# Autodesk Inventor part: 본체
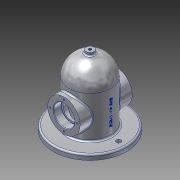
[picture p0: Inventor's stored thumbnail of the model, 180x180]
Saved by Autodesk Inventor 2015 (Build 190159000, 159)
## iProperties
Created: 2019-11
Part Number: 본체
Material: 알루미늄 6061
Document SubType Name: Modeling
Designer: LINEART-SSD.D4.16.05
Density: 2.7 g/cm^3
Appearance: 알루미늄 - 평지
Mass: 1106.12 g
Surface Area: 883.263 cm^2
Volume: 409.676 cm^3
Author: LINEART-SSD.D4.16.05
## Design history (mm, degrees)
sketch "스케치1"
  geometry: C1 r 70 at (0, 0); 1 further point
  constraints: 1 centre point, 1 coincident
  dimensions: "d0" = 140 diameter of C1
extrude "돌출1" new body sketch "스케치1" distance "d1" = 10; taper "d2" = 0 deg
sketch "스케치2"
  geometry: C1 r 40 at (0, 0); 1 further point
  constraints: 1 centre point, 1 coincident
  dimensions: "d3" = 80 diameter of C1
extrude "돌출2" join sketch "스케치2" distance "d4" = 80; taper "d5" = 0 deg
sketch "스케치6"
  geometry: L1 (90, -40)-(90, 40) reference; L2 (90, 0)-(90, -40); L3 (130, 0)-(90, 0); A1 r 40 centre (90, 0) between (90, -40) and (130, 0); 1 further point
  constraints: 4 end point, 2 point on circle, 1 centre point, 1 collinear, 1 horizontal, 1 midpoint
  dimensions: "d14" = 40 radius of A1 (derived)
revolve "회전2" sketch "스케치6" stored, may be unused: angle "d15" = 90 deg
node "작업 평면2"
sketch "스케치7"
  geometry: C1 r 7.5 at (0, 0); 1 further point
  constraints: 1 centre point, 1 coincident
  dimensions: "d16" = 15 diameter of C1
extrude "돌출4" join sketch "스케치7" distance "d17" = 5; taper "d18" = 0 deg; dims "d38" = 3, "d39" = 0
node "작업 평면3"
sketch "스케치9"
  geometry: L1 (10, -40)-(90, -40) reference; L2 (135, -7.5)-(135, 7.5) reference; C1 r 31 at (50, 0); 3 further points
  constraints: 2 midpoint, 1 centre point, 1 horizontal alignment, 1 vertical alignment
  dimensions: "d21" = 62 diameter of C1
extrude "돌출5" join sketch "스케치9" distance "d22" = 10; taper "d24" = 0 deg; dims "d23" = 30, "d25" = 0
sketch "스케치10"
  geometry: C1 r 31 at (0, 0) reference; C2 r 20 at (0, 0); 1 further point
  constraints: 1 centre point, 1 coincident
  dimensions: "d26" = 40 diameter of C2
extrude "돌출6" cut sketch "스케치10" distance "d27" = 15; taper "d28" = 0 deg
sketch "스케치11"
  geometry: C1 r 20 at (0, 0) reference; C2 r 16.5 at (0, 0); 1 further point
  constraints: 1 centre point, 1 coincident
  dimensions: "d29" = 33 diameter of C2
extrude "돌출7" cut sketch "스케치11" distance "d30" = 40; taper "d31" = 0 deg
sketch "스케치13"
  geometry: C1 r 30 at (0, 0); 1 further point
  constraints: 1 centre point, 1 coincident
  dimensions: "d32" = 60 diameter of C1
extrude "돌출8" cut sketch "스케치13" distance "d33" = 90; taper "d34" = 0 deg
sketch "스케치14"
  geometry: L1 (30, 90)-(-30, 90) reference; L2 (0, 90)-(30, 90); L3 (0, 90)-(0, 120); A1 r 30 centre (0, 90) between (30, 90) and (0, 120); 1 further point
  constraints: 5 end point, 2 point on circle, 1 centre point, 1 collinear, 1 midpoint, 1 perpendicular
revolve "회전3" sketch "스케치14" stored, may be unused: angle "d37" = 90 deg
sketch "스케치15"
  geometry: 2 further points
  constraints: 1 coincident
hole "구멍1" sketch "스케치15" at (0, 0) diameter "d40" = 5.188; stored, may be unused: countersink angle "d44" = 90 deg, drill point angle "d46" = 0 deg; dims "d41" = 12, "d42" = 4, "d43" = 2, "d45" = 16
sketch "스케치17" dims "d47" = 52
  geometry: C1 r 20 at (0, 0) reference; C2 r 31 at (0, 0) reference; 3 further points
  constraints: 2 vertical alignment, 1 coincident, 2 other
hole "구멍2" sketch "스케치17" at (0, 26) diameter "d48" = 3.242; stored, may be unused: countersink angle "d52" = 90 deg, drill point angle "d54" = 118 deg; dims "d49" = 8, "d50" = 4, "d51" = 2, "d53" = 10
sketch "스케치18"
  geometry: C1 r 4.5 at (0, -55); C2 r 4.5 at (0, 55); A1 r 55 centre (0, 0) between (0, -55) and (0, 55); 1 further point
  constraints: 3 centre point, 2 point on circle, 2 vertical alignment, 1 coincident
  dimensions: "d58" = 110 diameter of A1; "d61" = 9 diameter of C1; "d62" = 9 diameter of C2
extrude "돌출9" cut sketch "스케치18" distance "d63" = 90; taper "d64" = 0 deg
chamfer "모따기1" distance "d65" = 1; stored, may be unused: second distance "d66" = 2, angle "d67" = 45 deg
chamfer "모따기2" distance "d68" = 1; stored, may be unused: second distance "d69" = 2, angle "d70" = 45 deg
fillet "모깎기1" dims "d71" = 0.3
fillet "모깎기2" dims "d72" = 3
node "작업 평면4"
sketch "스케치19"
  geometry: L1 (-70, -10)-(70, -10) reference; L2 (7.5, 125)-(-7.5, 125) reference; 3 further points
  constraints: 1 midpoint, 1 vertical alignment, 1 other
  dimensions: "d73" = 50 distance from line of point (0, 40) L1
feature "엠보싱1" sketch "스케치19" dims "d17" = 5, "d74" = 0.5, "d75" = 0
node "솔리드1"
mirror "대칭1"
mirror "대칭2"
pattern_circular "원형 패턴1" dims angle "d56" = 360 deg
mirror "대칭3"
node "투영된 루프2"
node "투영된 루프3"
node "투영된 루프4"
